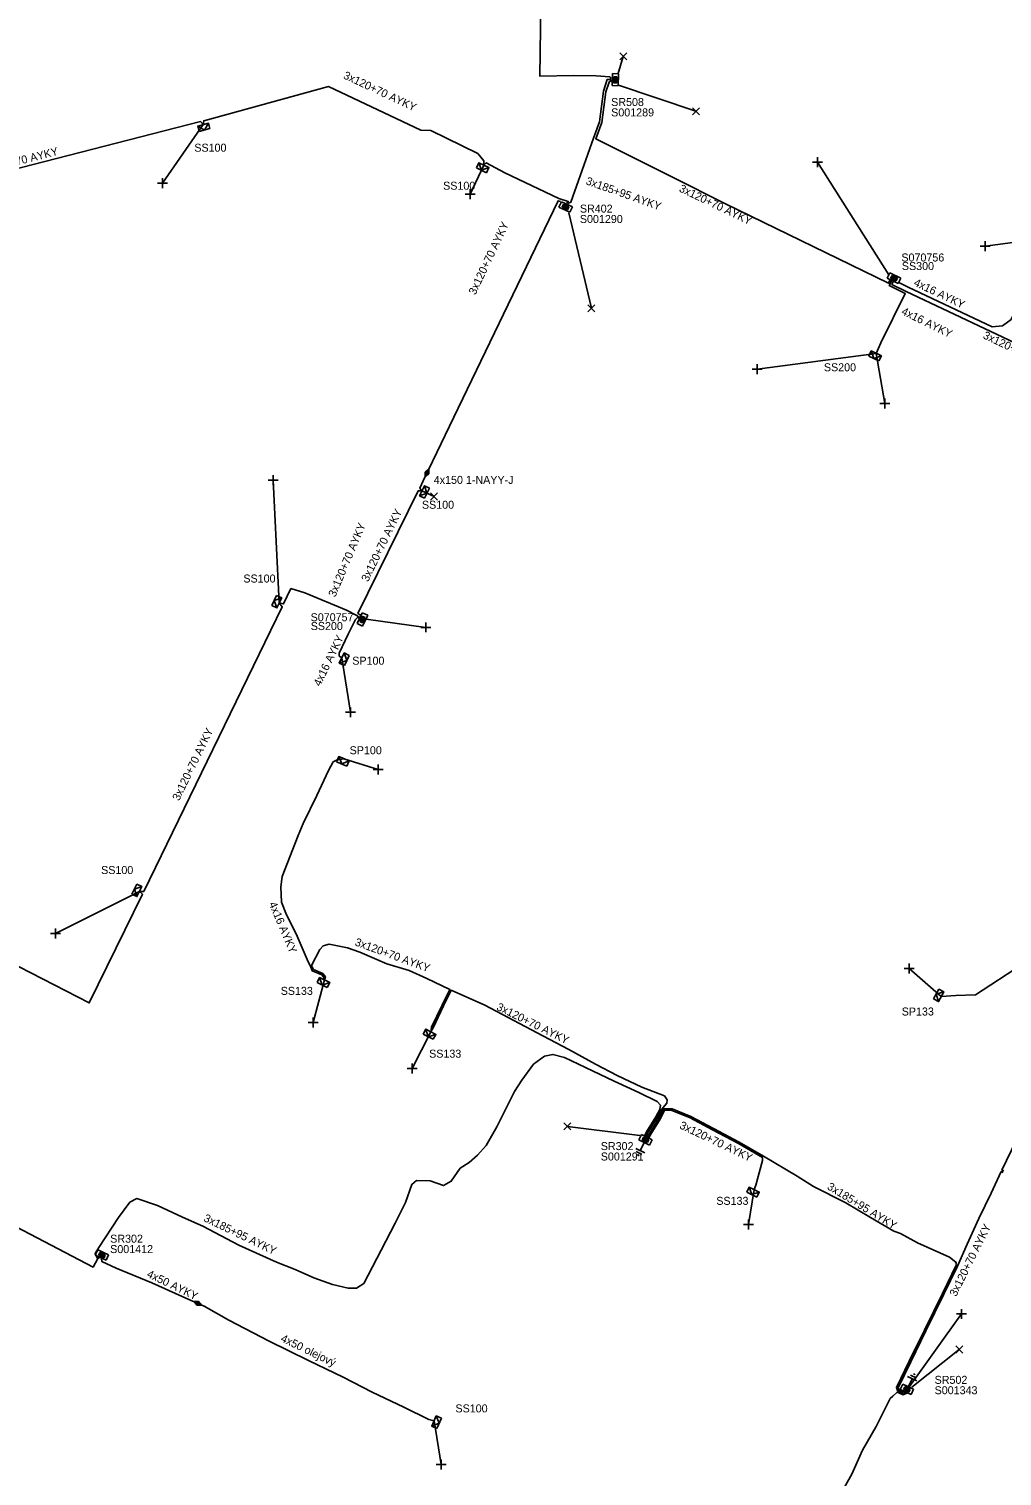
# Model space of a CAD drawing. Extents: x -763093 to -760976, y -1155572 to -1152009.
# Drawn here: x -762294.5 to -762173, y -1155041.4 to -1154860.6 of the extents above; entities that cross this region are included whole.
import ezdxf

# ---------------------------------------------------------------- set-up
doc = ezdxf.new("R2010")
doc.units = 0
for name, color, linetype in [('Vrstva 1', 7, 'Continuous'), ('Vrstva 14', 7, 'Continuous'), ('Vrstva 15', 7, 'Continuous'), ('Vrstva 19', 7, 'Continuous'), ('Vrstva 28', 7, 'Continuous'), ('Vrstva 29', 7, 'Continuous'), ('Vrstva 30', 7, 'Continuous'), ('Vrstva 31', 7, 'Continuous'), ('Vrstva 33', 7, 'Continuous'), ('Vrstva 34', 7, 'Continuous'), ('Vrstva 4', 7, 'Continuous'), ('Vrstva 5', 7, 'Continuous'), ('Vrstva 59', 7, 'Continuous'), ('Vrstva 6', 7, 'Continuous'), ('Vrstva 8', 7, 'Continuous'), ('Vrstva 9', 7, 'Continuous')]:
    doc.layers.add(name, color=color, linetype=linetype)

# ---------------------------------------------------------------- blocks, each defined once
blk = doc.blocks.new('NN870')
at = {"layer": 'Vrstva 4'}
for points in [[(0, -0.25), (0.5, 0), (0, 0.25), (-0.5, 0), (0, -0.25)], [(0.37, 0), (0, 0.19), (-0.36, 0), (0, -0.19), (0.37, 0)], [(0.24, 0), (0, 0.12), (-0.25, 0), (0, -0.12), (0.24, 0)], [(0.12, 0), (0, 0.06), (-0.13, 0), (0, -0.06), (0.12, 0)]]:
    blk.add_lwpolyline(points, dxfattribs=at)
blk = doc.blocks.new('NN800')
at = {"layer": 'Vrstva 1'}
for points in [[(-0.44, 0.44), (0.44, -0.44)], [(-0.44, -0.44), (0.44, 0.44)]]:
    blk.add_lwpolyline(points, dxfattribs=at)
blk = doc.blocks.new('NN620')
at = {"layer": 'Vrstva 8'}
for points in [[(0.75, 0), (-0.75, 0)], [(-0.75, 0), (-0.75, -0.75)], [(0.75, -0.75), (0.75, 0)], [(-0.75, -0.75), (0.75, -0.75)], [(0.37, -0.18), (-0.38, -0.18)], [(-0.38, -0.18), (-0.38, -0.56)], [(-0.38, -0.56), (0.37, -0.56)], [(0.32, -0.23), (-0.33, -0.23)], [(-0.33, -0.23), (-0.33, -0.51)], [(-0.33, -0.51), (0.32, -0.51)], [(0.27, -0.27), (-0.28, -0.27)], [(-0.28, -0.27), (-0.28, -0.46)], [(-0.28, -0.46), (0.27, -0.46)], [(0.23, -0.32), (-0.23, -0.32)], [(-0.23, -0.32), (-0.23, -0.42)], [(-0.23, -0.42), (0.23, -0.42)], [(-0.19, -0.37), (0.19, -0.37)], [(0.23, -0.42), (0.23, -0.32)], [(0.27, -0.46), (0.27, -0.27)], [(0.32, -0.51), (0.32, -0.23)], [(0.37, -0.56), (0.37, -0.18)]]:
    blk.add_lwpolyline(points, dxfattribs=at)
blk = doc.blocks.new('NN630')
at = {"layer": 'Vrstva 9'}
for points in [[(0, -0.7), (-0.7, 0)], [(-0.7, -0.7), (-0.7, 0), (0.7, 0), (0.7, -0.7)], [(-0.7, -0.7), (0.7, -0.7)], [(0, -0.7), (0.7, 0)]]:
    blk.add_lwpolyline(points, dxfattribs=at)
blk = doc.blocks.new('NN810')
at = {"layer": 'Vrstva 14'}
for points in [[(0, -0.64), (0, -1.89)], [(0.63, -1.89), (-0.62, -1.89)], [(0.39, -2.2), (-0.4, -2.2)], [(0, -2.52), (-0.12, -2.52)], [(0.14, -2.52), (0, -2.52)]]:
    blk.add_lwpolyline(points, dxfattribs=at)

msp = doc.modelspace()

# ---------------------------------------------------------------- linework, layer by layer
at = {"layer": 'Vrstva 5'}
for points in [[(-762244.34, -1154807.48), (-762244.06, -1154807.51), (-762242.57, -1154811.69), (-762240.66, -1154817.36), (-762238.6, -1154821.07), (-762233.72, -1154840.05), (-762232.04, -1154846.62), (-762230.54, -1154854.49), (-762230.71, -1154866.48), (-762226.47, -1154866.4), (-762223.66, -1154866.46), (-762221.96, -1154866.6), (-762221.77, -1154866.8)], [(-762221.77, -1154866.93), (-762222.27, -1154866.91), (-762222.73, -1154868.38), (-762223.23, -1154872.22), (-762223.97, -1154874.24), (-762226.82, -1154882.26), (-762227.2, -1154882.42)], [(-762221.78, -1154867.05), (-762222.05, -1154867.23), (-762222.44, -1154868.44), (-762222.94, -1154872.29), (-762223.69, -1154874.34), (-762214.12, -1154879.11), (-762207.5, -1154882.46), (-762187.13, -1154892.38), (-762186.95, -1154891.93)], [(-762359.29, -1154893.96), (-762358.38, -1154893.76), (-762355.07, -1154893.09), (-762338.76, -1154888.92), (-762338.46, -1154889.26), (-762338.41, -1154888.83), (-762310.89, -1154881.88), (-762310.64, -1154882.2), (-762310.56, -1154881.79), (-762273.08, -1154872.18), (-762272.75, -1154872.56), (-762272.68, -1154872.07), (-762257.1, -1154867.81), (-762245.54, -1154873.23), (-762244.31, -1154873.27), (-762238.44, -1154876.17), (-762237.69, -1154877.08), (-762237.69, -1154877.63), (-762237.38, -1154877.32), (-762235.08, -1154878.58), (-762228.32, -1154881.78), (-762227.14, -1154882.16), (-762227.31, -1154882.36)], [(-762244.79, -1154916.08), (-762244.65, -1154915.77), (-762240.9, -1154908), (-762228.41, -1154882.07), (-762228.12, -1154882.16)], [(-762185.87, -1154892.27), (-762184.67, -1154892.86), (-762174.21, -1154897.84), (-762172.9, -1154897.72), (-762171.8, -1154896.89), (-762166.96, -1154886.85), (-762167.25, -1154886.69)], [(-762186.73, -1154892.03), (-762187.05, -1154892.68), (-762185.05, -1154893.67), (-762188.08, -1154899.82), (-762188.66, -1154901.15)], [(-762186.52, -1154892.14), (-762186.71, -1154892.52), (-762184.92, -1154893.4), (-762174.36, -1154898.43), (-762150.14, -1154909.88), (-762150.02, -1154909.5)], [(-762245.42, -1154918.31), (-762245.67, -1154917.98), (-762245.49, -1154917.55), (-762244.79, -1154916.08)], [(-762253.08, -1154933.98), (-762253.15, -1154933.82), (-762253.41, -1154933.65), (-762245.89, -1154918.33), (-762245.42, -1154918.31)], [(-762338.8, -1154956.25), (-762339.01, -1154956.52), (-762332.46, -1154959.85), (-762332.1, -1154959.44), (-762332.11, -1154960.01), (-762321.9, -1154965.01), (-762321.38, -1154964.63), (-762321.4, -1154965.25), (-762301.62, -1154974.8), (-762286.97, -1154982.32), (-762280.33, -1154968.72), (-762280.71, -1154968.39), (-762280.17, -1154968.4), (-762262.87, -1154932.81), (-762263.24, -1154932.33), (-762262.71, -1154932.46), (-762261.78, -1154930.53), (-762260.03, -1154931.06), (-762254.84, -1154933.25), (-762253.57, -1154933.92), (-762253.29, -1154934.1), (-762253.2, -1154934.22)], [(-762253.2, -1154934.22), (-762253.48, -1154934.17), (-762253.72, -1154934.4), (-762254.63, -1154936.25), (-762255.77, -1154938.59), (-762255.76, -1154938.97), (-762255.43, -1154939.21)], [(-762257.57, -1154979.45), (-762257.67, -1154979.13), (-762257.92, -1154978.81), (-762259.11, -1154978.3), (-762259.34, -1154977.73), (-762259.61, -1154977.18), (-762260.99, -1154973.99), (-762262.42, -1154971.08), (-762262.96, -1154969.73), (-762263.03, -1154967.79), (-762262.87, -1154966.51), (-762260.87, -1154961.38), (-762260.26, -1154959.9), (-762258.53, -1154956.41), (-762257.11, -1154953.26), (-762256.5, -1154952.2), (-762256.08, -1154952), (-762255.17, -1154951.81)], [(-762162.86, -1154957.94), (-762166.26, -1154965.37), (-762166.92, -1154966.48), (-762166.81, -1154967.06), (-762166.02, -1154967.88), (-762166.02, -1154968.47), (-762167.3, -1154971.16), (-762168.8, -1154974.05), (-762170.39, -1154977.46), (-762176.29, -1154981.32), (-762178.72, -1154981.38), (-762180.56, -1154981.53)], [(-762217.38, -1154998.97), (-762217.19, -1154998.52), (-762216.02, -1154996.66), (-762215.49, -1154995.64), (-762214.82, -1154994.84), (-762214.8, -1154994.41), (-762215.12, -1154993.92), (-762217.95, -1154992.84), (-762221.04, -1154991.37), (-762223.74, -1154989.97), (-762227.08, -1154988.14), (-762230.32, -1154986.42), (-762237.56, -1154982.61), (-762241.77, -1154980.71), (-762242.72, -1154982.66), (-762244.03, -1154985.44), (-762244.3, -1154985.92), (-762244.21, -1154985.36), (-762242.9, -1154982.58), (-762241.95, -1154980.63), (-762244.8, -1154979.26), (-762247.01, -1154978.25), (-762249.81, -1154977.42), (-762253.18, -1154975.97), (-762254.73, -1154975.44), (-762256.99, -1154974.98), (-762257.76, -1154975.2), (-762258.19, -1154975.66), (-762259.2, -1154977.64), (-762258.95, -1154978.14), (-762257.8, -1154978.65), (-762257.47, -1154979.05), (-762257.57, -1154979.45)], [(-762285.77, -1155014.13), (-762286, -1155014.17), (-762286.23, -1155013.65), (-762285.79, -1155012.89), (-762283.31, -1155009.15), (-762281.9, -1155007.22), (-762281.02, -1155006.74), (-762278.44, -1155007.65), (-762275.32, -1155009.08), (-762272.8, -1155010.22), (-762268.29, -1155012.59), (-762263.58, -1155014.7), (-762261.27, -1155015.65), (-762258.93, -1155016.69), (-762256.61, -1155017.52), (-762254.63, -1155017.95), (-762253.59, -1155017.96), (-762252.69, -1155017.36), (-762250.5, -1155013.23), (-762248.77, -1155009.83), (-762247.47, -1155007.25), (-762246.66, -1155004.99), (-762246.08, -1155004.52), (-762244.4, -1155004.53), (-762242.72, -1155005.14), (-762241.75, -1155004.61), (-762240.63, -1155002.97), (-762239.51, -1155002.28), (-762238.48, -1155001.33), (-762237.4, -1155000.14), (-762236.06, -1154997.82), (-762233.85, -1154993.37), (-762232.96, -1154991.99), (-762231.47, -1154989.96), (-762230.13, -1154988.99), (-762229.05, -1154988.75), (-762227.62, -1154989.14), (-762224.1, -1154990.82), (-762221.41, -1154992.1), (-762218.34, -1154993.53), (-762216.04, -1154994.62), (-762215.63, -1154995.08), (-762215.71, -1154995.63), (-762216.19, -1154996.56), (-762217.37, -1154998.43), (-762217.56, -1154998.88)], [(-762217.2, -1154999.05), (-762217.01, -1154998.62), (-762215.84, -1154996.76), (-762215.22, -1154995.54), (-762214.15, -1154995.56), (-762211.82, -1154996.49), (-762209.01, -1154998), (-762205.8, -1154999.73), (-762202.74, -1155001.48), (-762198.56, -1155003.98), (-762196.52, -1155005.25), (-762192.45, -1155007.32), (-762189.37, -1155009.13), (-762186.48, -1155010.83), (-762185.64, -1155011.14), (-762183.5, -1155012.29), (-762179.5, -1155014.11), (-762178.73, -1155014.7), (-762178.64, -1155015.02), (-762180.4, -1155018.62), (-762182.65, -1155023.23), (-762184.54, -1155027.08), (-762186.15, -1155030.38), (-762186.03, -1155030.75), (-762185.32, -1155031.09), (-762185.07, -1155030.98)], [(-762203.92, -1155005.65), (-762203.7, -1155005.09), (-762202.87, -1155002.03), (-762202.89, -1155001.63), (-762205.89, -1154999.88), (-762209.11, -1154998.18), (-762211.9, -1154996.67), (-762214.19, -1154995.76), (-762215.1, -1154995.74), (-762215.67, -1154996.86), (-762216.83, -1154998.71), (-762217.02, -1154999.14)], [(-762172.75, -1155003.3), (-762172.97, -1155003.21), (-762171.18, -1154999.53)], [(-762185.28, -1155030.85), (-762185.32, -1155030.87), (-762185.86, -1155030.61), (-762185.93, -1155030.4), (-762184.36, -1155027.16), (-762182.47, -1155023.31), (-762180.22, -1155018.7), (-762178.51, -1155015.2), (-762177.32, -1155012.47), (-762175.86, -1155009.26), (-762174.31, -1155006.1), (-762173.05, -1155003.39), (-762172.83, -1155003.49)], [(-762285.45, -1155014.26), (-762285.42, -1155014.62), (-762283.61, -1155015.47), (-762279.14, -1155017.31), (-762275.36, -1155018.99), (-762273.42, -1155019.87)], [(-762273.42, -1155019.87), (-762272.63, -1155020.23), (-762269.53, -1155021.97), (-762264.51, -1155024.58), (-762259.6, -1155027), (-762255.26, -1155029.07), (-762251.62, -1155030.95), (-762247.7, -1155032.83), (-762244.56, -1155034.39), (-762243.91, -1155034.56)], [(-762193.03, -1155043.48), (-762191.74, -1155041.22), (-762190.39, -1155038.21), (-762188.66, -1155035.26), (-762186.92, -1155031.76), (-762186.59, -1155031.45), (-762186.06, -1155030.96), (-762185.32, -1155031.31), (-762184.83, -1155031.1)]]:
    msp.add_lwpolyline(points, dxfattribs=at)
at = {"layer": 'Vrstva 59'}
for points in [[(-762220.95, -1154866.28), (-762220.27, -1154864.03)], [(-762220.98, -1154867.6), (-762211.19, -1154870.88)], [(-762272.75, -1154872.56), (-762277.81, -1154879.88)], [(-762237.69, -1154877.63), (-762239.4, -1154881.25)], [(-762187.1, -1154891.32), (-762196, -1154877.25)], [(-762227.05, -1154883.6), (-762224.25, -1154895.5)], [(-762167.25, -1154886.69), (-762175.06, -1154887.75)], [(-762188.66, -1154901.15), (-762203.56, -1154903.13)], [(-762188.66, -1154901.15), (-762187.59, -1154907.4)], [(-762263.24, -1154932.33), (-762264, -1154917)], [(-762245.42, -1154918.31), (-762243.9, -1154919.03)], [(-762252.4, -1154934.36), (-762244.94, -1154935.38)], [(-762255.43, -1154939.21), (-762254.33, -1154946)], [(-762255.17, -1154951.81), (-762250.88, -1154953.13)], [(-762280.71, -1154968.39), (-762291.19, -1154973.63)], [(-762180.56, -1154981.53), (-762184.56, -1154978)], [(-762257.57, -1154979.45), (-762259, -1154984.75)], [(-762244.3, -1154985.92), (-762246.63, -1154990.5)], [(-762218.2, -1154998.88), (-762227.25, -1154997.75)], [(-762203.92, -1155005.65), (-762204.63, -1155010)], [(-762184.51, -1155030.25), (-762178.02, -1155021.19)], [(-762184.24, -1155030.34), (-762178.31, -1155025.63)], [(-762243.91, -1155034.56), (-762243, -1155040)]]:
    msp.add_lwpolyline(points, dxfattribs=at)
at = {"layer": 'Vrstva 9'}
msp.add_lwpolyline([(-762395.71, -1155089.89), (-762362.67, -1155098.86), (-762352.24, -1155103.81), (-762329.37, -1155058.32), (-762315.48, -1155030.67), (-762303.23, -1155006.6), (-762286.49, -1155015.33), (-762285.91, -1155014.24), (-762285.73, -1155014.22)], dxfattribs=at)

# ---------------------------------------------------------------- block references
at = {"layer": 'Vrstva 15'}
for p, rotation in [((-762217.32, -1154999.09), -25.922336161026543), ((-762184.99, -1155031), 154.52800274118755)]:
    msp.add_blockref('NN810', p, dxfattribs=dict(at, rotation=rotation))
at = {"layer": 'Vrstva 19'}
for p, rotation in [((-762244.79, -1154916.08), -115.46334502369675), ((-762273.42, -1155019.87), -26.18662786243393)]:
    msp.add_blockref('NN870', p, dxfattribs=dict(at, rotation=rotation))
at = {"layer": 'Vrstva 28'}
for p, rotation in [((-762221.64, -1154866.93), 88.06525835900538), ((-762227.31, -1154882.51), -25.153619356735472), ((-762186.62, -1154892.07), 153.3800666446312), ((-762253.19, -1154934.23), 64.34583890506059), ((-762217.32, -1154999.09), -25.922336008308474), ((-762285.55, -1155014.17), 155.21711259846), ((-762185, -1155030.95), 154.5280028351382)]:
    msp.add_blockref('NN620', p, dxfattribs=dict(at, rotation=rotation))
at = {"layer": 'Vrstva 31'}
for p, rotation in [((-762272.75, -1154872.56), 14.618577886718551), ((-762237.69, -1154877.63), -25.32737232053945), ((-762188.66, -1154901.15), -25.992011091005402), ((-762245.42, -1154918.31), 64.36329108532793), ((-762263.24, -1154932.33), -115.66494165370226), ((-762255.43, -1154939.21), 63.93131111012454), ((-762255.17, -1154951.81), -23.01810442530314), ((-762280.71, -1154968.39), -115.45891387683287), ((-762257.57, -1154979.45), -26.093666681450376), ((-762180.56, -1154981.53), -117.73493217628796), ((-762244.3, -1154985.92), -27.956473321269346), ((-762203.92, -1155005.65), -26.035305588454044), ((-762243.91, -1155034.56), 65.94970276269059)]:
    msp.add_blockref('NN630', p, dxfattribs=dict(at, rotation=rotation))
at = {"layer": 'Vrstva 34'}
for p in [(-762220.27, -1154864.03), (-762211.19, -1154870.88), (-762224.25, -1154895.5), (-762243.9, -1154919.03), (-762227.25, -1154997.75), (-762178.31, -1155025.63)]:
    msp.add_blockref('NN800', p, dxfattribs=at)
for p, rotation in [((-762196, -1154877.25), 45), ((-762277.81, -1154879.88), 45), ((-762239.4, -1154881.25), 44.99999995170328), ((-762175.06, -1154887.75), 45), ((-762203.56, -1154903.13), 45), ((-762187.59, -1154907.4), 45), ((-762264, -1154917), 45), ((-762244.94, -1154935.38), 44.99999995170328), ((-762254.33, -1154946), 45), ((-762250.88, -1154953.13), 45), ((-762291.19, -1154973.63), 44.99999995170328), ((-762184.56, -1154978), 45), ((-762259, -1154984.75), 45), ((-762246.63, -1154990.5), 45), ((-762204.63, -1155010), 45), ((-762178.02, -1155021.19), 45), ((-762243, -1155040), 45)]:
    msp.add_blockref('NN800', p, dxfattribs=dict(at, rotation=rotation))

# ---------------------------------------------------------------- texts
at = {"layer": 'Vrstva 29'}
for s, p in [('S001289', (-762221.78, -1154871.53)), ('S001290', (-762225.69, -1154884.85)), ('S070756', (-762185.53, -1154889.66)), ('S070757', (-762259.32, -1154934.62)), ('S001291', (-762223.08, -1155002.01)), ('S001412', (-762284.36, -1155013.58)), ('S001343', (-762181.38, -1155031.22))]:
    msp.add_text(s, height=1, dxfattribs=at).set_placement(p)
at = {"layer": 'Vrstva 30'}
for s, p in [('SR508', (-762221.78, -1154870.23)), ('SR402', (-762225.69, -1154883.55)), ('SS300', (-762185.47, -1154890.73)), ('SS200', (-762259.31, -1154935.72)), ('SR302', (-762223.08, -1155000.71)), ('SR302', (-762284.36, -1155012.28)), ('SR502', (-762181.38, -1155029.92))]:
    msp.add_text(s, height=1, dxfattribs=at).set_placement(p)
at = {"layer": 'Vrstva 33'}
for s, p in [('SS100', (-762273.85, -1154875.94)), ('SS100', (-762242.77, -1154880.69)), ('SS200', (-762195.21, -1154903.38)), ('SS100', (-762245.42, -1154920.56)), ('SS100', (-762267.72, -1154929.78)), ('SP100', (-762254.12, -1154940.05)), ('SP100', (-762254.45, -1154951.24)), ('SS100', (-762285.49, -1154966.21)), ('SS133', (-762263.06, -1154981.31)), ('SP133', (-762185.49, -1154983.89)), ('SS133', (-762244.52, -1154989.16)), ('SS133', (-762208.65, -1155007.55)), ('SS100', (-762241.23, -1155033.49))]:
    msp.add_text(s, height=1, dxfattribs=at).set_placement(p)
at = {"layer": 'Vrstva 6'}
for s, rotation, p in [('3x120+70 AYKY', 334.88, (-762255.32, -1154866.74)), ('3x120+70 AYKY', 14.396, (-762300.32, -1154878.77)), ('3x185+95 AYKY', 340.456, (-762225.03, -1154879.99)), ('3x120+70 AYKY', 334.425, (-762213.39, -1154880.87)), ('3x120+70 AYKY', 64.668, (-762238.74, -1154893.91)), ('4x16 AYKY', 334.51, (-762184.08, -1154892.63)), ('4x16 AYKY', 333.775, (-762185.62, -1154896.21)), ('3x120+70 AYKY', 334.512, (-762175.42, -1154899.22)), ('3x120+70 AYKY', 64.205, (-762252.15, -1154929.76)), ('3x120+70 AYKY', 67.122, (-762256.24, -1154931.67)), ('4x16 AYKY', 64.332, (-762258.12, -1154942.83)), ('3x120+70 AYKY', 64.077, (-762275.76, -1154957.13)), ('4x16 AYKY', 292.882, (-762264.56, -1154969.92)), ('3x120+70 AYKY', 339.862, (-762253.88, -1154975.1)), ('3x120+70 AYKY', 333.716, (-762236.19, -1154983.14)), ('3x120+70 AYKY', 334.525, (-762213.33, -1154997.95)), ('3x185+95 AYKY', 328.516, (-762194.89, -1155005.53)), ('3x185+95 AYKY', 334.172, (-762272.77, -1155009.54)), ('3x120+70 AYKY', 63.62, (-762178.69, -1155019.09)), ('4x50 AYKY', 334.185, (-762279.87, -1155016.52)), ('4x50 olejový', 334.186, (-762263.15, -1155024.57))]:
    msp.add_text(s, height=1, rotation=rotation, dxfattribs=at).set_placement(p)
msp.add_text('4x150 1-NAYY-J', height=1, dxfattribs=at).set_placement((-762243.94, -1154917.45))

doc.saveas('drawing.dxf')
